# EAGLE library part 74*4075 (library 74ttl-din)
Triple 3-input OR
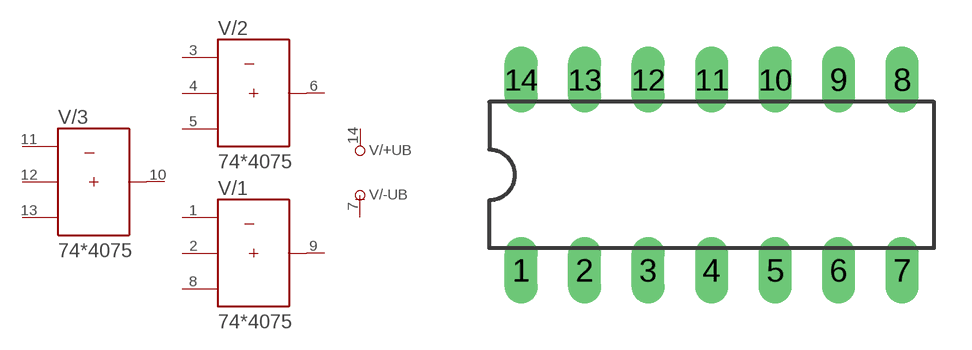
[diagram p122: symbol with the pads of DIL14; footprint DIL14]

Designator prefix V; gates /+UB=+UB /-UB=-UB /1=4075 /2=4075 /3=4075

## 744075N  [DIL14]
1  /1:A  in
2  /1:B  in
3  /2:A  in
4  /2:B  in
5  /2:C  in
6  /2:Y  out
7  /-UB:-UB  pwr
8  /1:C  in
9  /1:Y  out
10  /3:Y  out
11  /3:A  in
12  /3:B  in
13  /3:C  in
14  /+UB:+UB  pwr

## Footprint DIL14 (pad centres in mm)
Dual In Line Package
drill 0.813 long: 1 -7.62,-3.81; 2 -5.08,-3.81; 3 -2.54,-3.81; 4 0,-3.81; 5 2.54,-3.81; 6 5.08,-3.81; 7 7.62,-3.81; 8 7.62,3.81; 9 5.08,3.81; 10 2.54,3.81; 11 0,3.81; 12 -2.54,3.81; 13 -5.08,3.81; 14 -7.62,3.81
